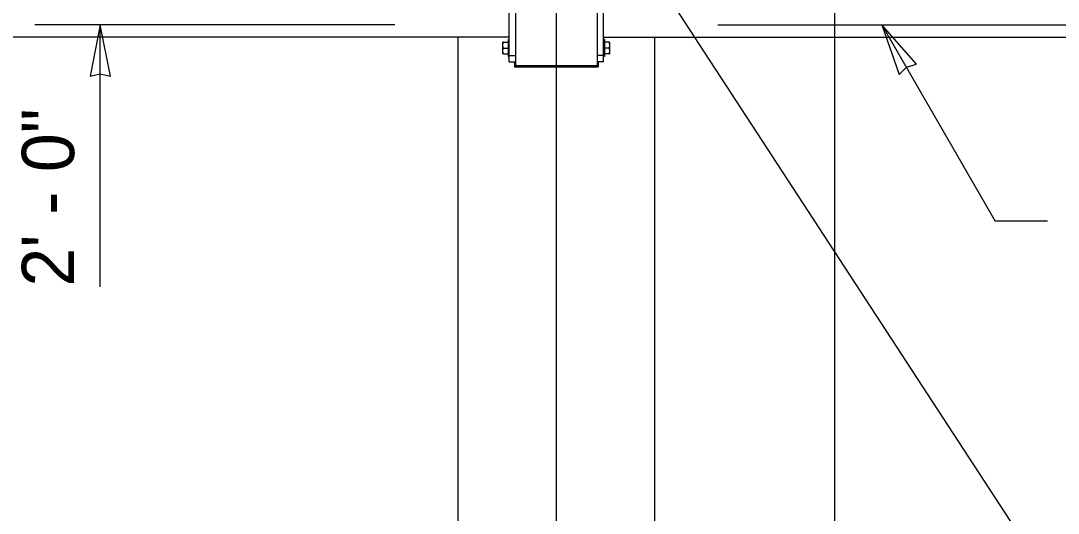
# Model space of a CAD drawing. Extents: x 99862 to 104211, y 98939 to 111076.
# Drawn here: x 101176.8 to 101493.9, y 104186.6 to 104337.2 of the extents above; entities that cross this region are included whole.
import ezdxf

# ---------------------------------------------------------------- set-up
doc = ezdxf.new("R2010")
doc.units = 0
for name, color, linetype in [('Level 15', 7, 'Continuous'), ('Level 20', 7, 'Continuous'), ('Level 3', 7, 'Continuous'), ('Level 4', 7, 'Continuous'), ('Level 6', 7, 'Continuous'), ('Level 9', 7, 'Continuous')]:
    doc.layers.add(name, color=color, linetype=linetype)

msp = doc.modelspace()

# ---------------------------------------------------------------- linework, layer by layer
at = {"layer": 'Level 15'}
for p, q in [((101425.5, 104455.89), (101425.5, 103662.4)), ((101519.55, 104122.56), (101342.34, 104394.21)), ((101340.5, 103587.9), (101340.5, 104388.39)), ((101291.12, 104335.89), (101181.12, 104335.89)), ((101201.12, 104255.89), (101201.12, 104335.89)), ((101389.87, 104335.89), (101540.24, 104335.89)), ((101439.96, 104335.89), (101474.6, 104275.89)), ((101490.6, 104275.89), (101474.6, 104275.89))]:
    msp.add_line(p, q, dxfattribs=at)
for points in [[(101201.12, 104335.89), (101198.04, 104320.17), (101201.12, 104320.89), (101204.21, 104320.17)], [(101439.96, 104335.89), (101445.27, 104320.77), (101447.56, 104322.97), (101450.59, 104323.9)]]:
    msp.add_lwpolyline(points, close=True, dxfattribs=at)
at = {"layer": 'Level 3'}
for p, q in [((101310.5, 103662.43), (101310.5, 104332.14)), ((101370.5, 104332.14), (101370.5, 103662.43)), ((101327.68, 104324.64), (101327.68, 104323.08)), ((101327.68, 104323.08), (101353.31, 104323.08)), ((101353.31, 104324.64), (101353.31, 104323.08))]:
    msp.add_line(p, q, dxfattribs=at)
at = {"layer": 'Level 4'}
for p, q in [((101328, 104348.39), (101328, 104323.39)), ((101353, 104348.39), (101353, 104323.39)), ((101353, 104323.39), (101328, 104323.39))]:
    msp.add_line(p, q, dxfattribs=at)
at = {"layer": 'Level 6'}
for p, q in [((101326.12, 104324.64), (101326.12, 104347.14)), ((101354.87, 104324.64), (101354.87, 104347.14)), ((101326.12, 104332.14), (100443.11, 104332.14)), ((101354.87, 104332.14), (101687.88, 104332.14)), ((101326.12, 104326.52), (101328, 104326.52)), ((101354.87, 104326.52), (101353, 104326.52)), ((101326.12, 104324.64), (101328, 104324.64)), ((101354.87, 104324.64), (101353, 104324.64))]:
    msp.add_line(p, q, dxfattribs=at)
at = {"layer": 'Level 9'}
for p, q in [((101324.17, 104329.73), (101324.17, 104330.57)), ((101324.17, 104329.65), (101324.17, 104329.73)), ((101324.17, 104327.96), (101324.17, 104329.65)), ((101324.33, 104330.57), (101325.73, 104330.57)), ((101325.73, 104331.42), (101325.73, 104326.22)), ((101325.73, 104331.42), (101326.12, 104331.42)), ((101355.26, 104331.42), (101354.87, 104331.42)), ((101355.26, 104331.42), (101355.26, 104326.22)), ((101356.67, 104330.57), (101355.26, 104330.57)), ((101356.82, 104329.73), (101356.82, 104330.57)), ((101356.82, 104329.65), (101356.82, 104329.73)), ((101356.82, 104327.96), (101356.82, 104329.65)), ((101324.17, 104327.9), (101324.17, 104327.96)), ((101324.17, 104327.05), (101324.17, 104327.9)), ((101324.33, 104328.81), (101325.73, 104328.81)), ((101324.33, 104327.05), (101325.73, 104327.05)), ((101325.73, 104326.22), (101326.12, 104326.22)), ((101355.26, 104326.22), (101354.87, 104326.22)), ((101356.67, 104328.81), (101355.26, 104328.81)), ((101356.67, 104327.05), (101355.26, 104327.05)), ((101356.82, 104327.9), (101356.82, 104327.96)), ((101356.82, 104327.05), (101356.82, 104327.9))]:
    msp.add_line(p, q, dxfattribs=at)
for points in [[(101324.33, 104330.57), (101324.23, 104330.57), (101324.17, 104330.57), (101324.17, 104330.57)], [(101324.17, 104329.73), (101324.17, 104330.02), (101324.23, 104330.29), (101324.33, 104330.57)], [(101324.33, 104328.81), (101324.23, 104329.08), (101324.17, 104329.36), (101324.17, 104329.65)], [(101356.67, 104330.57), (101356.76, 104330.57), (101356.82, 104330.57), (101356.82, 104330.57)], [(101356.82, 104329.73), (101356.82, 104330.02), (101356.76, 104330.29), (101356.67, 104330.57)], [(101356.67, 104328.81), (101356.76, 104329.08), (101356.82, 104329.36), (101356.82, 104329.65)], [(101324.17, 104327.96), (101324.17, 104328.25), (101324.23, 104328.53), (101324.33, 104328.81)], [(101324.33, 104327.05), (101324.23, 104327.33), (101324.17, 104327.61), (101324.17, 104327.9)], [(101324.17, 104327.05), (101324.17, 104327.05), (101324.17, 104327.05), (101324.17, 104327.05)], [(101324.33, 104327.05), (101324.23, 104327.05), (101324.17, 104327.05), (101324.17, 104327.05)], [(101356.82, 104327.96), (101356.82, 104328.25), (101356.76, 104328.53), (101356.67, 104328.81)], [(101356.67, 104327.05), (101356.76, 104327.33), (101356.82, 104327.61), (101356.82, 104327.9)], [(101356.67, 104327.05), (101356.76, 104327.05), (101356.82, 104327.05), (101356.82, 104327.05)], [(101356.82, 104327.05), (101356.82, 104327.05), (101356.82, 104327.05), (101356.82, 104327.05)]]:
    msp.add_open_spline(points, degree=2, dxfattribs=at)

# ---------------------------------------------------------------- texts
at = {"layer": 'Level 20'}
msp.add_text('2\' - 0"', height=16, rotation=90, dxfattribs=at).set_placement((101193.12, 104255.89))

doc.saveas('drawing.dxf')
